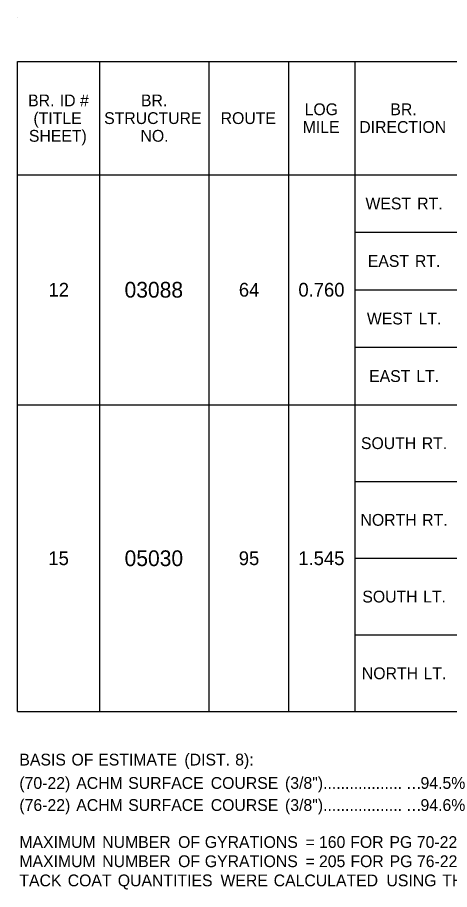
# Model space of a CAD drawing. Extents: x 540541 to 1930787, y -1948574 to 596640.
# Drawn here: x 559673.3 to 559893, y -1946443.7 to -1946000.3 of the extents above; entities that cross this region are included whole.
import ezdxf

# ---------------------------------------------------------------- set-up
doc = ezdxf.new("R2010")
doc.units = 0
doc.layers.add('Default', color=7, linetype='Continuous')
doc.layers.add('R_Border', color=7, linetype='Continuous')

msp = doc.modelspace()

# ---------------------------------------------------------------- linework, layer by layer
at = {"layer": 'Default'}
for p, q in [((559673.34, -1946022.69), (560560.1, -1946022.69)), ((559673.34, -1946353.21), (559673.34, -1946022.69)), ((559715.27, -1946353.21), (559715.27, -1946022.69)), ((559770.84, -1946353.21), (559770.84, -1946022.69)), ((559811.3, -1946353.21), (559811.3, -1946022.69)), ((559844.94, -1946353.21), (559844.94, -1946022.69)), ((559673.34, -1946080.21), (560091.13, -1946080.21)), ((559770.84, -1946197.21), (559770.84, -1946080.21)), ((559844.94, -1946080.21), (559894.67, -1946080.21)), ((559844.94, -1946109.46), (560560.1, -1946109.46)), ((559844.94, -1946138.71), (560560.1, -1946138.71)), ((559844.94, -1946167.96), (560560.1, -1946167.96)), ((559673.34, -1946197.21), (559715.27, -1946197.21)), ((559673.34, -1946197.21), (560479.18, -1946197.21)), ((559770.84, -1946197.21), (559844.94, -1946197.21)), ((559844.94, -1946197.21), (559894.67, -1946197.21)), ((559844.94, -1946236.21), (560560.1, -1946236.21)), ((559844.94, -1946275.21), (560560.1, -1946275.21)), ((559844.94, -1946314.21), (560193.02, -1946314.21)), ((559673.34, -1946353.21), (560560.1, -1946353.21))]:
    msp.add_line(p, q, dxfattribs=at)
at = {"layer": 'R_Border'}
msp.add_line((559673.34, -1946000.26), (559673.34, -1946000.26), dxfattribs=at)

# ---------------------------------------------------------------- texts
at = {"layer": 'Default'}
for s, height, p in [('BR.', 6, (559678.78, -1946045.45)), (' ID', 6, (559692.64, -1946045.45)), (' #', 6, (559702.94, -1946045.45)), ('BR.', 6, (559736.12, -1946045.45)), ('LOG', 6, (559819.29, -1946049.95)), ('BR.', 6, (559862.87, -1946049.95)), ('(TITLE', 6, (559681.47, -1946054.45)), ('STRUCTURE', 6, (559717.41, -1946054.45)), ('ROUTE', 6, (559776.61, -1946054.45)), ('MILE', 6, (559818.32, -1946058.95)), ('DIRECTION', 6, (559847.08, -1946058.95)), ('SHEET)', 6, (559679.15, -1946063.45)), ('NO.', 6, (559735.89, -1946063.45)), ('WEST', 6, (559850.23, -1946097.84)), (' RT.', 6, (559874.28, -1946097.84)), ('EAST', 6, (559851.39, -1946127.09)), (' RT.', 6, (559873.12, -1946127.09)), ('12', 7, (559689.13, -1946142.21)), ('03088', 8, (559727.77, -1946142.71)), ('64', 7, (559785.87, -1946142.21)), ('0.760', 7, (559816.13, -1946142.21)), ('WEST', 6, (559850.93, -1946156.34)), (' LT.', 6, (559874.98, -1946156.34)), ('EAST', 6, (559852.08, -1946185.59)), (' LT.', 6, (559873.82, -1946185.59)), ('SOUTH', 6, (559847.92, -1946219.71)), (' RT.', 6, (559876.59, -1946219.71)), ('NORTH', 6, (559847.69, -1946258.71)), (' RT.', 6, (559876.82, -1946258.71)), ('15', 7, (559689.06, -1946278.71)), ('05030', 8, (559727.79, -1946279.21)), ('95', 7, (559785.83, -1946278.71)), ('1.545', 7, (559816.09, -1946278.71)), ('SOUTH', 6, (559848.62, -1946297.71)), (' LT.', 6, (559877.29, -1946297.71)), ('NORTH', 6, (559848.39, -1946336.71)), (' LT.', 6, (559877.52, -1946336.71)), ('BASIS', 6, (559674.32, -1946380.59)), (' OF', 6, (559698.58, -1946380.59)), (' ESTIMATE', 6, (559712.16, -1946380.59)), (' (DIST.', 6, (559755.97, -1946380.59)), (' 8):', 6, (559781.78, -1946380.59)), ('(70-22)', 6, (559674.32, -1946392.47)), (' ACHM', 6, (559701.02, -1946392.47)), (' SURFACE', 6, (559727.41, -1946392.47)), (' COURSE', 6, (559769.35, -1946392.47)), (' (3/8")..................', 6, (559807.1, -1946392.47)), ('94.5%', 6, (559878.2, -1946392.47)), ('…', 6, (559870.8, -1946392.47)), ('(76-22)', 6, (559674.32, -1946403.69)), (' (3/8")..................', 6, (559807.1, -1946403.69)), (' ACHM', 6, (559701.02, -1946403.69)), (' SURFACE', 6, (559727.41, -1946403.69)), (' COURSE', 6, (559769.35, -1946403.69)), ('94.6%', 6, (559878.2, -1946403.69)), ('…', 6, (559870.8, -1946403.69)), ('MAXIMUM', 6, (559674.32, -1946422.51)), (' NUMBER', 6, (559714.2, -1946422.51)), (' OF', 6, (559752.75, -1946422.51)), (' GYRATIONS', 6, (559766.34, -1946422.51)), (' =', 6, (559817.61, -1946422.51)), (' 160', 6, (559824.36, -1946422.51)), (' FOR', 6, (559840.27, -1946422.51)), (' PG', 6, (559860.18, -1946422.51)), (' 70-22', 6, (559874.1, -1946422.51)), ('MAXIMUM', 6, (559674.32, -1946432.26)), (' NUMBER', 6, (559714.2, -1946432.26)), (' OF', 6, (559752.75, -1946432.26)), (' GYRATIONS', 6, (559766.34, -1946432.26)), (' =', 6, (559817.61, -1946432.26)), (' 205', 6, (559824.36, -1946432.26)), (' FOR', 6, (559840.34, -1946432.26)), (' PG', 6, (559860.25, -1946432.26)), (' 76-22', 6, (559874.16, -1946432.26)), ('TACK', 6, (559674.32, -1946442.01)), (' COAT', 6, (559696.66, -1946442.01)), (' QUANTITIES', 6, (559722.11, -1946442.01)), (' WERE', 6, (559774.31, -1946442.01)), (' CALCULATED', 6, (559801.34, -1946442.01)), (' USING', 6, (559858.66, -1946442.01)), (' THE', 6, (559887.01, -1946442.01))]:
    msp.add_text(s, height=height, dxfattribs=at).set_placement(p)

doc.saveas('drawing.dxf')
